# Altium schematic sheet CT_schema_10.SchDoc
size 274 x 160 mm
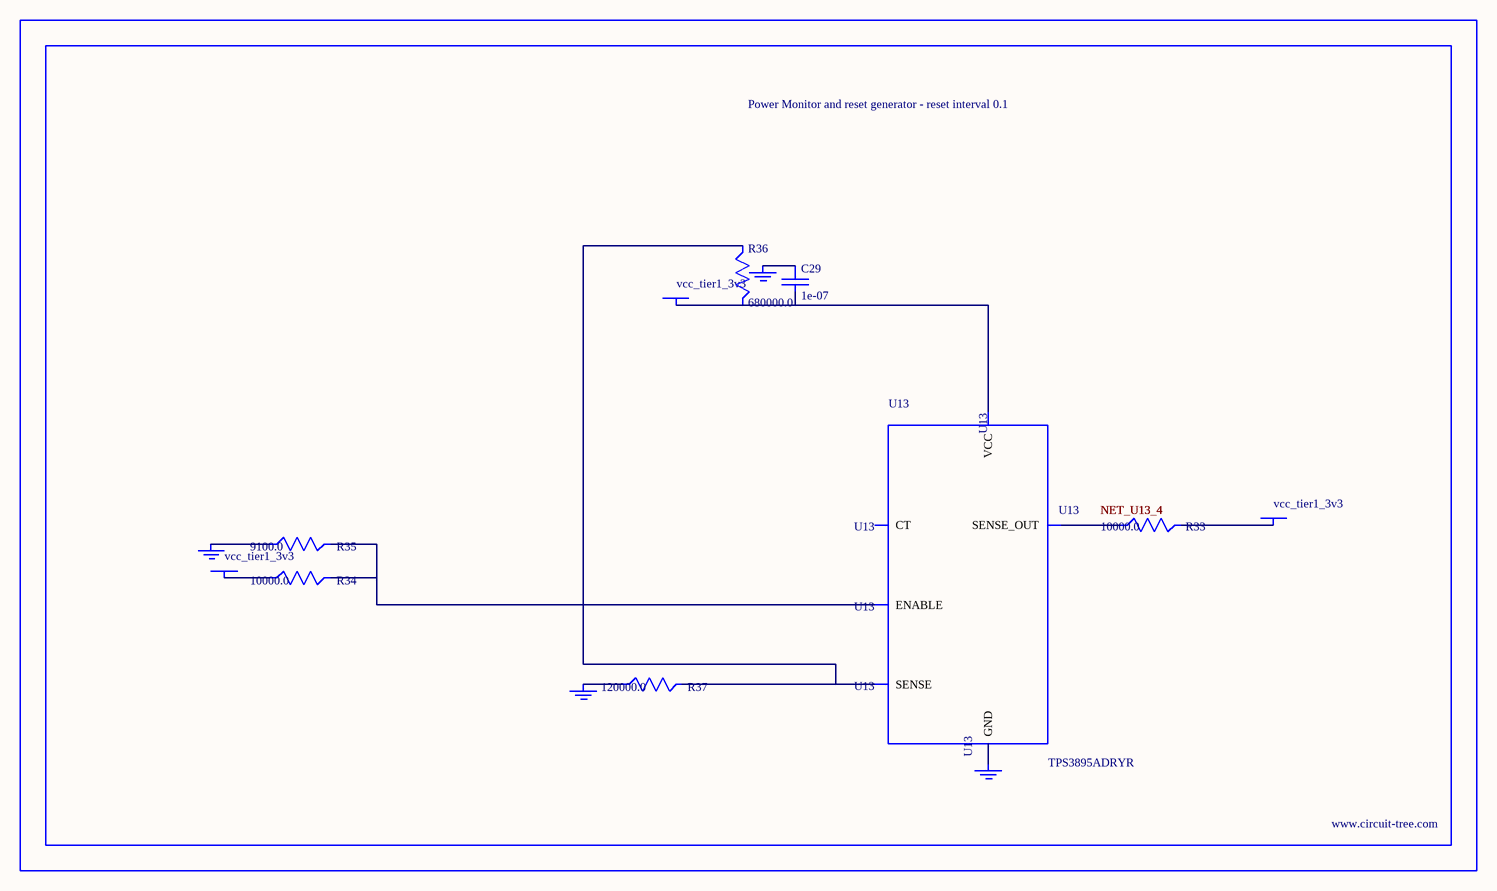
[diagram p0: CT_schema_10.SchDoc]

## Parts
BORDER9  (no value)
C29  1e-07  [C0402]
GND_INSTANCE_9_0  (no value)
GND_INSTANCE_9_1  (no value)
GND_INSTANCE_9_2  (no value)
GND_INSTANCE_9_3  (no value)
POWER_INSTANCE_9_0  vcc_tier1_3v3
POWER_INSTANCE_9_1  vcc_tier1_3v3
POWER_INSTANCE_9_2  vcc_tier1_3v3
R33  10000.0  [R0603]
R34  10000.0  [R0603]
R35  9100.0  [R0603]
R36  680000.0  [R0603]
R37  120000.0  [R0603]
U13  TPS3895ADRYR  [SON-6]

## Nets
NetC29_1: C29.1 GND_INSTANCE_9_2.0(GND)
NetC29_2: C29.2 POWER_INSTANCE_9_2.0(PWR) R36.2 U13.6(VCC)
NetGND_INSTANCE_9_0_0: GND_INSTANCE_9_0.0(GND) R35.1
NetGND_INSTANCE_9_1_0: GND_INSTANCE_9_1.0(GND) R37.1
NetGND_INSTANCE_9_3_0: GND_INSTANCE_9_3.0(GND) U13.2(GND)
NetPOWER_INSTANCE_9_0_0: POWER_INSTANCE_9_0.0(PWR) R34.1
NetPOWER_INSTANCE_9_1_0: POWER_INSTANCE_9_1.0(PWR) R33.2
NetR33_1: R33.1 U13.4(SENSE_OUT)
NetR34_2: R34.2 R35.2 U13.1(ENABLE)
NetR36_1: R36.1 R37.2 U13.3(SENSE)

Not connected (* = marked no-connect by the designer): U13 5(CT)

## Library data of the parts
BORDER9 = BORDER_PAGE9
C29 = C0402C104K3RACTU
GND_INSTANCE_9_0-GND_INSTANCE_9_3 = GND
POWER_INSTANCE_9_0-POWER_INSTANCE_9_2 = PWR
R33 R34 = RC0603JR-0710KL
R35 = RC0603JR-079K1L
R36 = RC0603JR-07680KL
R37 = RC0603JR-07120KL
